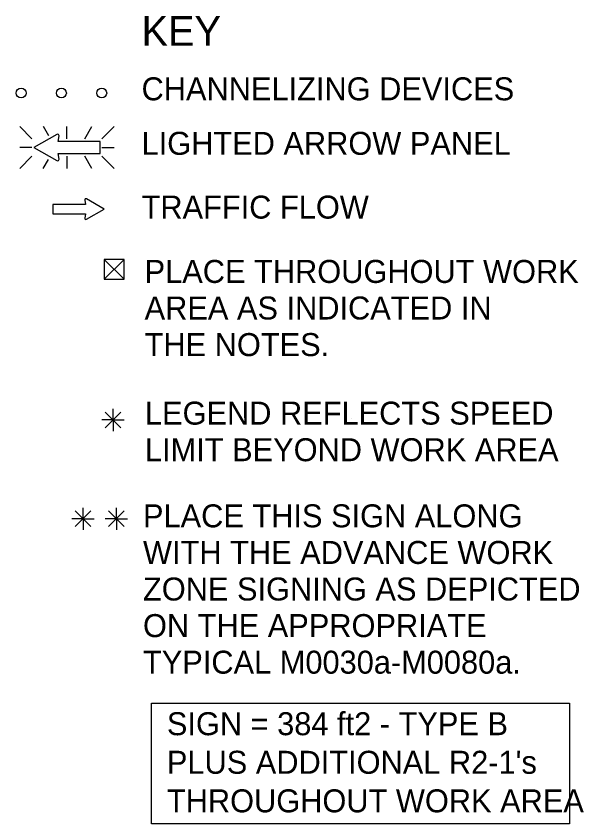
# Model space of a CAD drawing. Extents: x 16364 to 18480, y 5564 to 6927.
# Drawn here: x 17180.2 to 17409.7, y 6587.6 to 6914.4 of the extents above; entities that cross this region are included whole.
import ezdxf

# ---------------------------------------------------------------- set-up
doc = ezdxf.new("R2010")
doc.units = 0
for name, color, linetype in [('MT_SCRATCH_LEVEL_E', 7, 'Continuous'), ('TRAFFIC_SIGNS_PR', 7, 'Continuous'), ('TYPICAL_TEXT_DIMEN_EX', 7, 'Continuous'), ('TYPICAL_TEXT_DIMEN_PR', 7, 'Continuous')]:
    doc.layers.add(name, color=color, linetype=linetype)

msp = doc.modelspace()

# ---------------------------------------------------------------- linework, layer by layer
at = {"layer": 'MT_SCRATCH_LEVEL_E'}
for p, q in [((17207.95, 6839.97), (17208.26, 6838.19)), ((17215.87, 6836.34), (17208.63, 6840.45)), ((17208.26, 6838.19), (17195.01, 6838.19)), ((17195.01, 6838.19), (17195.01, 6834.45)), ((17208.63, 6832.19), (17215.87, 6836.34)), ((17195.01, 6834.45), (17208.26, 6834.45)), ((17208.26, 6834.45), (17207.95, 6832.67))]:
    msp.add_line(p, q, dxfattribs=at)
for centre, start, end in [((17208.41, 6840.05), 60.4248, 189.9638), ((17208.41, 6832.6), 170.0362, 299.7731)]:
    msp.add_arc(centre, 0.463, start, end, dxfattribs=at)
at = {"layer": 'TRAFFIC_SIGNS_PR'}
for p, q in [((17181.68, 6869.72), (17186.62, 6864.79)), ((17193.45, 6865.9), (17191.24, 6869.73)), ((17200.77, 6864.79), (17200.77, 6869.73)), ((17208, 6864.79), (17210.85, 6869.73)), ((17214.92, 6864.79), (17219.85, 6869.73)), ((17186.62, 6861.24), (17181.68, 6861.24)), ((17214.92, 6861.24), (17219.85, 6861.24)), ((17181.68, 6852.75), (17186.62, 6857.68)), ((17191.19, 6852.75), (17193.31, 6856.41)), ((17200.77, 6857.68), (17200.77, 6852.75)), ((17210.9, 6852.75), (17208.05, 6857.68)), ((17214.92, 6857.68), (17219.85, 6852.74))]:
    msp.add_line(p, q, dxfattribs=at)
for points in [[(17196.69, 6866.51), (17187.4, 6861.24), (17196.7, 6855.91)], [(17197.57, 6856.54), (17197.17, 6858.81), (17214.18, 6858.81), (17214.18, 6863.61), (17197.17, 6863.61), (17197.57, 6865.89)]]:
    msp.add_lwpolyline(points, dxfattribs=at)
for centre in [(17182.25, 6883.27), (17198.55, 6883.27), (17214.85, 6883.27)]:
    msp.add_circle(centre, 2, dxfattribs=at)
for centre, radius, start, end in [((17196.98, 6865.99), 0.598, 350.7308, 118.8916), ((17196.98, 6856.44), 0.597, 241.4833, 9.9593)]:
    msp.add_arc(centre, radius, start, end, dxfattribs=at)
at = {"layer": 'TYPICAL_TEXT_DIMEN_EX'}
msp.add_lwpolyline([(17234.95, 6636.45), (17403.96, 6636.45), (17403.96, 6587.62), (17234.95, 6587.62)], close=True, dxfattribs=at)
at = {"layer": 'TYPICAL_TEXT_DIMEN_PR'}
for p, q in [((17215.88, 6815.98), (17223.88, 6807.98)), ((17215.88, 6807.98), (17223.88, 6815.98)), ((17216.23, 6754.21), (17222.6, 6747.83)), ((17222.6, 6754.21), (17216.23, 6747.83)), ((17219.42, 6751.02), (17219.42, 6755.48)), ((17219.42, 6751.02), (17214.88, 6751.02)), ((17219.42, 6751.02), (17222.6, 6751.02)), ((17219.42, 6751.02), (17223.89, 6751.02)), ((17219.42, 6751.02), (17219.42, 6746.52)), ((17207.28, 6711.07), (17207.28, 6715.52)), ((17220.78, 6711.07), (17220.78, 6715.52)), ((17204.09, 6714.25), (17210.46, 6707.88)), ((17210.46, 6714.25), (17204.09, 6707.88)), ((17223.97, 6714.25), (17217.59, 6707.88)), ((17217.6, 6714.25), (17223.97, 6707.88)), ((17207.28, 6711.07), (17202.74, 6711.07)), ((17207.28, 6711.07), (17210.46, 6711.07)), ((17207.28, 6711.07), (17211.75, 6711.07)), ((17207.28, 6711.07), (17207.28, 6706.57)), ((17220.78, 6711.07), (17216.25, 6711.07)), ((17220.78, 6711.07), (17223.97, 6711.07)), ((17220.78, 6711.07), (17225.26, 6711.07)), ((17220.78, 6711.07), (17220.78, 6706.57))]:
    msp.add_line(p, q, dxfattribs=at)
msp.add_lwpolyline([(17215.88, 6815.98), (17215.88, 6807.98), (17223.88, 6807.98), (17223.88, 6815.98)], close=True, dxfattribs=at)
msp.add_open_spline([(17315.92, 6751.61), (17315.94, 6751.61), (17315.95, 6751.61), (17315.95, 6751.61)], degree=2, dxfattribs=at)

# ---------------------------------------------------------------- texts
at = {"layer": 'TYPICAL_TEXT_DIMEN_EX'}
for s, height, p in [('KEY', 12, (17230.94, 6902.37)), ('CHANNELIZING DEVICES', 9.3, (17230.94, 6880.32)), ('LIGHTED ARROW PANEL', 9.3, (17230.94, 6858.27)), ('TRAFFIC FLOW', 9.3, (17230.94, 6832.47)), ('PLACE THROUGHOUT WORK', 9.3, (17232.18, 6806.45)), ('AREA AS INDICATED IN', 9.3, (17232.18, 6791.65)), ('THE NOTES.', 9.3, (17232.18, 6776.85)), ('LEGEND REFLECTS SPEED', 9.3, (17232.31, 6749.12)), ('LIMIT BEYOND WORK AREA', 9.3, (17232.31, 6734.32)), ('PLACE THIS SIGN ALONG', 9.3, (17231.52, 6707.57)), ('WITH THE ADVANCE WORK', 9.3, (17231.52, 6692.77)), ('ZONE SIGNING AS DEPICTED', 9.3, (17231.52, 6677.97)), ('ON THE APPROPRIATE', 9.3, (17231.52, 6663.17)), ('TYPICAL M0030a-M0080a.', 9.3, (17231.52, 6648.37)), ('SIGN = 384 ft2 - TYPE B', 9.3, (17241.18, 6623.48)), ("PLUS ADDITIONAL R2-1's", 9.3, (17241.18, 6607.88)), ('THROUGHOUT WORK AREA', 9.3, (17241.18, 6592.28))]:
    msp.add_text(s, height=height, dxfattribs=at).set_placement(p)

doc.saveas('drawing.dxf')
